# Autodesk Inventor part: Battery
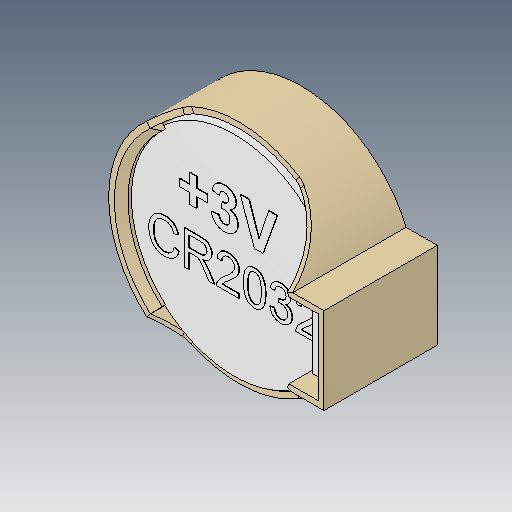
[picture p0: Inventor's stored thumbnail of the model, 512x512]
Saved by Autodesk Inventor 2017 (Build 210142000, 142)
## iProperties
Created: 2005-12
Part Number: Battery
Material: Generic
Document SubType Name: Modeling
Designer: DanielSeverino
Density: 1 g/cm^3
Appearance: Default
Author: DanielSeverino
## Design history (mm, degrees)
feature "Solid1"
body "Solid2"
